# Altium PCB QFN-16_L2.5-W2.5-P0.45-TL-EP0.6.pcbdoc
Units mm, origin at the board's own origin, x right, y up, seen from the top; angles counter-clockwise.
Board outline 16.08 x 15.8 mm, 2 copper layers (Top Layer, Bottom Layer), stack 0 mm thick; 1 components, 0 nets, 17 pads, 0 vias.
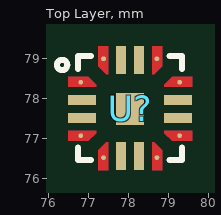
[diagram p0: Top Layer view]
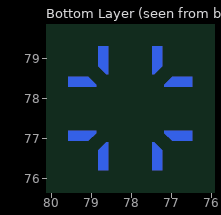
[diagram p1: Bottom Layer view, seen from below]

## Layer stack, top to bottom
Top Layer: signal copper (thickness not stored)
Bottom Layer: signal copper (thickness not stored)

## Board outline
85.934,69.85 69.85,69.85 69.85,85.651 85.934,85.651

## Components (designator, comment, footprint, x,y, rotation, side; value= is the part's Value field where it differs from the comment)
U? "" QFN-16_L2.5-W2.5-P0.45-TL-EP0.6 78.034,77.732 r0 top

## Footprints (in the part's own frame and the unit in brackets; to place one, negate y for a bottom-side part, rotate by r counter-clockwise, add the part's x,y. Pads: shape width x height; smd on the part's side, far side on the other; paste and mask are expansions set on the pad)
QFN-16_L2.5-W2.5-P0.45-TL-EP0.6 [mm]
  round 0.118 smd: 1(-1.236,0.667) 4(-1.236,-0.667) 5(-0.667,-1.218) 8(0.668,-1.218) 9(1.236,-0.667) 12(1.236,0.668) 13(0.668,1.254) 16(-0.666,1.254)
  rect 0.7x0.25 smd paste+0 mask+0.05: 2(-1.2,0.225) 3(-1.2,-0.225) 10(1.2,-0.225) 11(1.2,0.225)
  rect 0.25x0.7 smd paste+0 mask+0.05: 6(-0.225,-1.182) 7(0.225,-1.182) 14(0.225,1.218) 15(-0.225,1.218)
  rect 0.7x0.8 smd paste+0 mask+0.05: 17(0,0)
  Top Layer region: 0.801,1.066 0.801,1.569 0.55,1.568 0.55,1.568 0.55,0.868 0.603,0.868
  Top Layer region: -0.549,1.568 -0.799,1.569 -0.799,1.067 -0.601,0.868 -0.548,0.868 -0.548,1.568
  Top Layer region: -0.85,0.602 -1.048,0.8 -1.551,0.8 -1.55,0.549 -1.55,0.549 -0.85,0.549
  Top Layer region: -1.55,-0.8 -1.048,-0.8 -0.849,-0.602 -0.849,-0.549 -1.55,-0.549 -1.55,-0.549
  Top Layer region: 0.801,-1.532 0.801,-1.03 0.602,-0.832 0.55,-0.832 0.55,-1.532 0.55,-1.532
  Top Layer region: -0.8,-1.532 -0.8,-1.03 -0.602,-0.832 -0.549,-0.832 -0.549,-1.532 -0.549,-1.532
  Top Layer region: 1.551,0.801 1.048,0.801 0.85,0.602 0.85,0.55 1.55,0.55 1.55,0.55
  Top Layer region: 1.551,-0.8 1.048,-0.8 0.85,-0.602 0.85,-0.549 1.55,-0.549 1.55,-0.549
  Bottom Layer region: 0.801,1.066 0.801,1.569 0.55,1.568 0.55,1.568 0.55,0.868 0.603,0.868
  Bottom Layer region: -0.549,1.568 -0.799,1.569 -0.799,1.067 -0.601,0.868 -0.548,0.868 -0.548,1.568
  Bottom Layer region: -0.85,0.602 -1.048,0.8 -1.551,0.8 -1.55,0.549 -1.55,0.549 -0.85,0.549
  Bottom Layer region: -1.55,-0.8 -1.048,-0.8 -0.849,-0.602 -0.849,-0.549 -1.55,-0.549 -1.55,-0.549
  Bottom Layer region: 0.801,-1.532 0.801,-1.03 0.602,-0.832 0.55,-0.832 0.55,-1.532 0.55,-1.532
  Bottom Layer region: -0.8,-1.532 -0.8,-1.03 -0.602,-0.832 -0.549,-0.832 -0.549,-1.532 -0.549,-1.532
  Bottom Layer region: 1.551,0.801 1.048,0.801 0.85,0.602 0.85,0.55 1.55,0.55 1.55,0.55
  Bottom Layer region: 1.551,-0.8 1.048,-0.8 0.85,-0.602 0.85,-0.549 1.55,-0.549 1.55,-0.549
  Multi-Layer region: 0.801,1.066 0.801,1.569 0.55,1.568 0.55,1.568 0.55,0.868 0.603,0.868
  Multi-Layer region: -0.549,1.568 -0.799,1.569 -0.799,1.067 -0.601,0.868 -0.548,0.868 -0.548,1.568
  Multi-Layer region: -0.85,0.602 -1.048,0.8 -1.551,0.8 -1.55,0.549 -1.55,0.549 -0.85,0.549
  Multi-Layer region: -1.55,-0.8 -1.048,-0.8 -0.849,-0.602 -0.849,-0.549 -1.55,-0.549 -1.55,-0.549
  Multi-Layer region: 0.801,-1.532 0.801,-1.03 0.602,-0.832 0.55,-0.832 0.55,-1.532 0.55,-1.532
  Multi-Layer region: -0.8,-1.532 -0.8,-1.03 -0.602,-0.832 -0.549,-0.832 -0.549,-1.532 -0.549,-1.532
  Multi-Layer region: 1.551,0.801 1.048,0.801 0.85,0.602 0.85,0.55 1.55,0.55 1.55,0.55
  Multi-Layer region: 1.551,-0.8 1.048,-0.8 0.85,-0.602 0.85,-0.549 1.55,-0.549 1.55,-0.549
  silkscreen extent -1.83,-1.28 1.3,1.32

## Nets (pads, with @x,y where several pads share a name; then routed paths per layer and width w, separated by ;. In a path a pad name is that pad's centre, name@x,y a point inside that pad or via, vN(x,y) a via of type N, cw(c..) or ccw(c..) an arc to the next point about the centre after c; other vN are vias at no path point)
pads on no net: U?.1 U?.2 U?.3 U?.4 U?.5 U?.6 U?.7 U?.8 U?.9 U?.10 U?.11 U?.12 U?.13 U?.14 U?.15 U?.16 U?.17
